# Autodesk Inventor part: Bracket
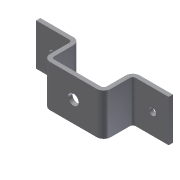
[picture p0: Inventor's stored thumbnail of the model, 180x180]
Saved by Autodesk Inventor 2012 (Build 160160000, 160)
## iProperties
Created: 2010-05
Part Number: Bracket
Document SubType Name: Modeling
Designer: CADSoft
Density: 1 g/cm^3
Material: Default
Author: CADSoft
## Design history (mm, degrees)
sketch "Sketch1"
  geometry: L1 (-476.866, 0)-(-189.366, 0); L2 (-189.366, 0)-(-189.366, -208); L3 (-189.366, -208)-(185.634, -208); L4 (185.634, -208)-(185.634, 0); L5 (185.634, 0)-(473.134, 0); L6 (473.134, 0)-(473.134, -30); L7 (473.134, -30)-(215.634, -30); L8 (215.634, -30)-(215.634, -238); L9 (215.634, -238)-(-219.366, -238); L10 (-219.366, -238)-(-219.366, -30); L11 (-219.366, -30)-(-476.866, -30); L12 (-476.866, -30)-(-476.866, 0); 1 further point
  constraints: 24 end point, 8 parallel, 5 equal length, 1 collinear, 1 horizontal, 1 horizontal alignment, 1 perpendicular
  dimensions: "d0" = 950 distance between parallel lines of L6 L12; "d1" = 238 distance between parallel lines of L1 L9; "d2" = 30 distance of L5.end L6.end; "d3" = 30 distance between parallel lines of L9 L3; "d4" = 30 distance between parallel lines of L4 L8; "d5" = 435 distance of L8.end L9.end
extrude "Extrusion1" new body sketch "Sketch1" stored distance "d6" = 300; taper "d7" = 0 deg
fillet "Fillet1" dims "d8" = 20
fillet "Fillet2" dims "d9" = 50
hole "Hole1" diameter "d12" = 75; stored, may be unused: countersink angle "d16" = 90 deg, drill point angle "d18" = 118 deg; dims "d10" = 150, "d11" = 217.5, "d13" = 6, "d14" = 4, "d15" = 2, "d17" = 8
hole "Hole2" diameter "d21" = 50; stored, may be unused: countersink angle "d25" = 90 deg, drill point angle "d27" = 118 deg; dims "d19" = 150, "d20" = 120, "d22" = 6, "d23" = 4, "d24" = 2, "d26" = 8
mirror "Mirror1"
body "Solid1"
